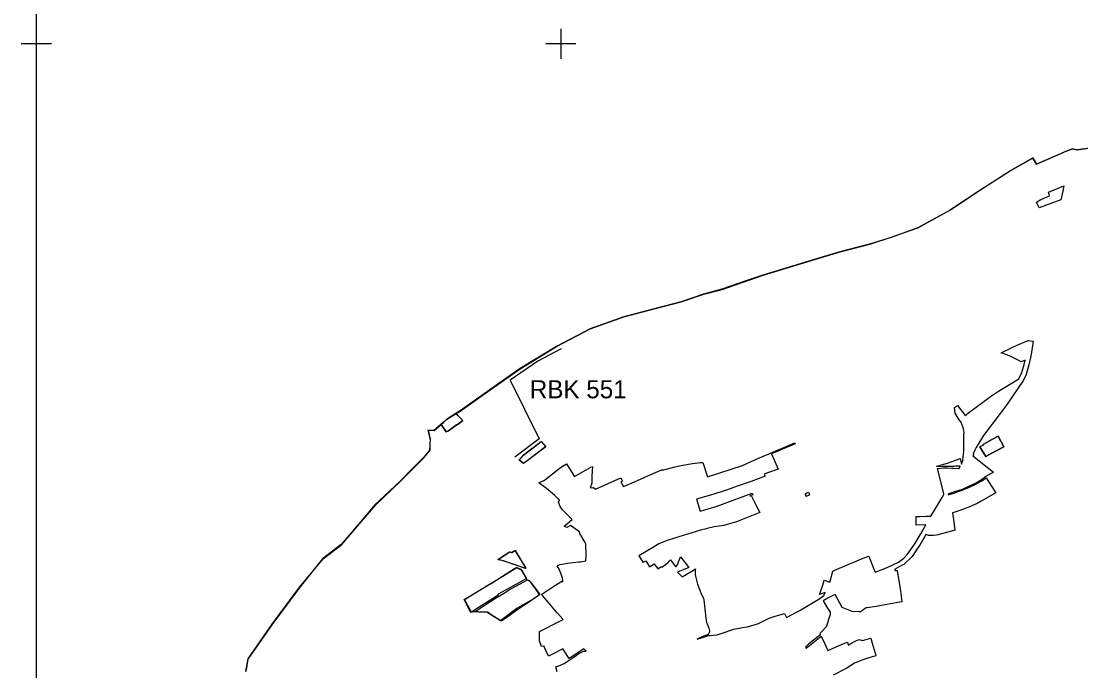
# Model space of a CAD drawing. Extents: x -478490 to -472450, y -1118050 to -1109550.
# Drawn here: x -478490 to -474975, y -1115880 to -1113725 of the extents above; entities that cross this region are included whole.
import ezdxf

# ---------------------------------------------------------------- set-up
doc = ezdxf.new("R2010")
doc.units = 0
for name, color, linetype in [('hranice kú', 7, 'Continuous'), ('Implicitní', 7, 'Continuous'), ('ObPÚ', 7, 'Continuous')]:
    doc.layers.add(name, color=color, linetype=linetype)

msp = doc.modelspace()

# ---------------------------------------------------------------- linework, layer by layer
at = {"layer": 'hranice kú'}
for p, q in [((-475022.9, -1114156.5), (-475122.4, -1114199.6)), ((-475002.4, -1114148.5), (-475022.9, -1114156.5)), ((-474987.2, -1114152.5), (-475002.4, -1114148.5)), ((-474886, -1114137.7), (-474987.2, -1114152.5)), ((-475134, -1114179), (-475207.8, -1114221.5)), ((-475122.4, -1114199.6), (-475134, -1114179)), ((-475207.8, -1114221.5), (-475309.6, -1114286.2)), ((-475309.6, -1114286.2), (-475401.1, -1114346.7)), ((-475401.1, -1114346.7), (-475408.2, -1114351.3)), ((-475408.2, -1114351.3), (-475516.2, -1114410.6)), ((-475516.2, -1114410.6), (-475603.8, -1114442.4)), ((-475603.8, -1114442.4), (-475675.9, -1114464.8)), ((-475748.8, -1114483.6), (-475774.2, -1114490.1)), ((-475675.9, -1114464.8), (-475748.8, -1114483.6)), ((-475851.9, -1114513.6), (-476030.1, -1114567.2)), ((-475774.2, -1114490.1), (-475851.9, -1114513.6)), ((-476089.1, -1114587.7), (-476165.8, -1114614.4)), ((-476030.1, -1114567.2), (-476089.1, -1114587.7)), ((-476165.8, -1114614.4), (-476226.9, -1114630.6)), ((-476300.5, -1114656.1), (-476390.6, -1114678.9)), ((-476226.9, -1114630.6), (-476300.5, -1114656.1)), ((-476390.6, -1114678.9), (-476491.3, -1114705.4)), ((-476491.3, -1114705.4), (-476602.9, -1114745.8)), ((-476602.9, -1114745.8), (-476714.7, -1114803.6)), ((-476714.7, -1114803.6), (-476835.3, -1114877.2)), ((-476835.3, -1114877.2), (-476889.8, -1114915.9)), ((-476889.8, -1114915.9), (-477034.1, -1115017.7)), ((-477079.5, -1115046.1), (-477089.2, -1115054.5)), ((-477047.8, -1115026.2), (-477079.5, -1115046.1)), ((-477034.1, -1115017.7), (-477047.8, -1115026.2)), ((-477121, -1115082.3), (-477141, -1115082)), ((-477141, -1115082), (-477133.6, -1115111.5)), ((-477098.4, -1115062.6), (-477121, -1115082.3)), ((-477089.2, -1115054.5), (-477098.4, -1115062.6)), ((-477133.6, -1115111.5), (-477134.2, -1115129.3)), ((-477134.7, -1115147.1), (-477142.3, -1115156.6)), ((-477134.2, -1115129.3), (-477134.7, -1115147.1)), ((-477155, -1115172.4), (-477210.7, -1115227.9)), ((-477142.3, -1115156.6), (-477155, -1115172.4)), ((-477233.1, -1115250.4), (-477267, -1115282.3)), ((-477229.4, -1115246.9), (-477233.1, -1115250.4)), ((-477216.6, -1115233.9), (-477229.4, -1115246.9)), ((-477214.6, -1115231.9), (-477216.6, -1115233.9)), ((-477210.7, -1115227.9), (-477214.6, -1115231.9)), ((-477267, -1115282.3), (-477317.9, -1115330.4)), ((-477317.9, -1115330.4), (-477350, -1115369.3)), ((-477350, -1115369.3), (-477428.5, -1115460.9)), ((-477428.5, -1115460.9), (-477490.1, -1115508.2)), ((-477490.1, -1115508.2), (-477566.2, -1115601.8)), ((-477566.2, -1115601.8), (-477658.2, -1115726.7)), ((-477658.2, -1115726.7), (-477738.5, -1115840.6)), ((-477738.5, -1115840.6), (-477743.9, -1115876.8)), ((-477743.9, -1115876.8), (-477745.7, -1115882.6))]:
    msp.add_line(p, q, dxfattribs=at)
at = {"layer": 'Implicitní'}
for p, q in [((-478440.1, -1113750.1), (-478440.1, -1113850.1)), ((-478440.1, -1113750.1), (-478440.1, -1113850.1)), ((-478440.1, -1113750.1), (-478440.1, -1113850.1)), ((-478440.1, -1113750.1), (-478440.1, -1113850.1)), ((-478440.1, -1113750.1), (-478440.1, -1113850.1)), ((-478440.1, -1113750.1), (-478440.1, -1113850.1)), ((-478440.1, -1113750.1), (-478440.1, -1113850.1)), ((-476700.1, -1113750.1), (-476700.1, -1113850.1)), ((-476700.1, -1113750.1), (-476700.1, -1113850.1)), ((-476700.1, -1113750.1), (-476700.1, -1113850.1)), ((-476700.1, -1113750.1), (-476700.1, -1113850.1)), ((-476700.1, -1113750.1), (-476700.1, -1113850.1)), ((-476700.1, -1113750.1), (-476700.1, -1113850.1)), ((-476700.1, -1113750.1), (-476700.1, -1113850.1)), ((-478390.1, -1113800.1), (-478490.1, -1113800.1)), ((-478390.1, -1113800.1), (-478490.1, -1113800.1)), ((-478390.1, -1113800.1), (-478490.1, -1113800.1)), ((-478390.1, -1113800.1), (-478490.1, -1113800.1)), ((-478390.1, -1113800.1), (-478490.1, -1113800.1)), ((-478390.1, -1113800.1), (-478490.1, -1113800.1)), ((-476650.1, -1113800.1), (-476750.1, -1113800.1)), ((-476650.1, -1113800.1), (-476750.1, -1113800.1)), ((-476650.1, -1113800.1), (-476750.1, -1113800.1)), ((-476650.1, -1113800.1), (-476750.1, -1113800.1)), ((-476650.1, -1113800.1), (-476750.1, -1113800.1)), ((-476650.1, -1113800.1), (-476750.1, -1113800.1))]:
    msp.add_line(p, q, dxfattribs=at)
msp.add_lwpolyline([(-478440.1, -1118000.1), (-472500.1, -1118000.1), (-472500.1, -1109600.1), (-478440.1, -1109600.1)], close=True, dxfattribs=at)
msp.add_lwpolyline([(-476699, -1114811.9), (-476776, -1114852.7), (-476868.5, -1114915.7), (-476771.5, -1115110.6), (-476852.1, -1115171.5)], dxfattribs=at)
at = {"layer": 'ObPÚ'}
for p, q in [((-476795.8, -1115142.9), (-476765.1, -1115119.2)), ((-476765.1, -1115119.2), (-476749.5, -1115136)), ((-476823.6, -1115164), (-476813.4, -1115156.5)), ((-476813.4, -1115156.5), (-476795.8, -1115142.9)), ((-476749.5, -1115136), (-476807.4, -1115179.7)), ((-476838.6, -1115180.4), (-476823.6, -1115164)), ((-476823.5, -1115192.3), (-476838.6, -1115180.4)), ((-476807.4, -1115179.7), (-476823.5, -1115192.3)), ((-476909, -1115510.7), (-476870.1, -1115484.8)), ((-476870.1, -1115484.8), (-476863.3, -1115487.6)), ((-476863.3, -1115487.6), (-476852.1, -1115480.5)), ((-476852.1, -1115480.5), (-476817.4, -1115537.3)), ((-476900.7, -1115512.2), (-476909, -1115510.7)), ((-476891.2, -1115515.2), (-476900.7, -1115512.2)), ((-476878.5, -1115519.2), (-476891.2, -1115515.2)), ((-476816.7, -1115540.2), (-476878.5, -1115519.2)), ((-476817.4, -1115537.3), (-476816.7, -1115540.2))]:
    msp.add_line(p, q, dxfattribs=at)
for points in [[(-477744.4, -1115881.6), (-477737.4, -1115839.5), (-477657.3, -1115725.4), (-477565.5, -1115600.8), (-477486.9, -1115507), (-477426, -1115461.1), (-477348, -1115368.5), (-477315.2, -1115330.2), (-477231.4, -1115250.6), (-477154.2, -1115173.6), (-477134.2, -1115148.8), (-477133.2, -1115130.3), (-477132.1, -1115111.9), (-477138.9, -1115081.3), (-477119.7, -1115082.7), (-477097.2, -1115062.7), (-477080.6, -1115086.8), (-477072.5, -1115083.8), (-477045.9, -1115063.6), (-477043.9, -1115064.1), (-477025.3, -1115049.6), (-477043.5, -1115030.7), (-477047.5, -1115026.1), (-477033.7, -1115018.2), (-476934, -1114947.9), (-476834.4, -1114877.8), (-476714.6, -1114803.8), (-476602.9, -1114745.9), (-476491.3, -1114705.5), (-476390.2, -1114678.8), (-476300.7, -1114655.7), (-476225.2, -1114630.7), (-476164.4, -1114614.7), (-476028.4, -1114567.7), (-475850.6, -1114513.7), (-475773.2, -1114490.1), (-475675.4, -1114464.4), (-475603.9, -1114441.6), (-475515.6, -1114410.1), (-475407.7, -1114350.6), (-475310.4, -1114285.4), (-475208.2, -1114220.8), (-475134, -1114178.4), (-475121.9, -1114199.1), (-475023.6, -1114156.4), (-475002.8, -1114148.9), (-474998, -1114149.5), (-474990.2, -1114150.6), (-474989.1, -1114150.8), (-474987.5, -1114151), (-474886.4, -1114137.2)], [(-475031.6, -1114270.7), (-475035.2, -1114288.3), (-475041.6, -1114317.3), (-475071, -1114328.2), (-475113.6, -1114343.8), (-475122.4, -1114325.3), (-475107.2, -1114316.9), (-475078.7, -1114304.2), (-475082.7, -1114291.8), (-475031.6, -1114270.7)], [(-475148.1, -1114784.1), (-475132.8, -1114786.1), (-475134.1, -1114794.3), (-475139.6, -1114829.2), (-475141.4, -1114840.6), (-475147, -1114864.5), (-475156.6, -1114896.8), (-475164.7, -1114915.7), (-475219.8, -1114995.7), (-475246.4, -1115030.8), (-475297.9, -1115099.1), (-475322.5, -1115139.2), (-475323.4, -1115141.1), (-475326.2, -1115147.8), (-475332.4, -1115160.1), (-475329.7, -1115162.2), (-475332.8, -1115166.5), (-475264.7, -1115220.3), (-475289.6, -1115235.6), (-475304.6, -1115246.6), (-475313.5, -1115251.8), (-475327.3, -1115259.4), (-475332.9, -1115262), (-475368.8, -1115277.8), (-475390.2, -1115285.2), (-475413.5, -1115293), (-475413.9, -1115295.5), (-475414.6, -1115296.5), (-475396.8, -1115290.7), (-475381.9, -1115285.4), (-475368.1, -1115280.4), (-475352.2, -1115273.9), (-475342, -1115269.3), (-475326, -1115262.1), (-475313, -1115254.8), (-475303.1, -1115249.2), (-475289.4, -1115239.2), (-475271.1, -1115267.1), (-475256.4, -1115289.3), (-475305.6, -1115316.7), (-475319, -1115324.5), (-475352.1, -1115339), (-475379.3, -1115349.1), (-475393.3, -1115353.4), (-475400.3, -1115356), (-475396.5, -1115385.4), (-475392.7, -1115413), (-475404.3, -1115416.8), (-475436.9, -1115425.3), (-475448.5, -1115428.4), (-475454.5, -1115429.6), (-475463.7, -1115430.8), (-475472.8, -1115431.1), (-475479.9, -1115430.5), (-475488.1, -1115428), (-475488.8, -1115427.8), (-475491.2, -1115432.3), (-475508.3, -1115461.2), (-475522.4, -1115482.1), (-475534.8, -1115500.6), (-475562.6, -1115526.6), (-475569.6, -1115530.7), (-475585.2, -1115539.6), (-475592.6, -1115543.6), (-475588.6, -1115546.6), (-475584.2, -1115546.5), (-475575.5, -1115600.7), (-475574.6, -1115607), (-475568.6, -1115650.4), (-475601.1, -1115656.6), (-475624.5, -1115661.2), (-475654.2, -1115666.4), (-475684.3, -1115671.3), (-475687.2, -1115670.6), (-475693.7, -1115674.8), (-475699, -1115680.1), (-475705.7, -1115683.9), (-475709.8, -1115683.9), (-475733.4, -1115683.1), (-475767, -1115669.8), (-475790, -1115626.6), (-475799.8, -1115631.5), (-475804, -1115633.4), (-475810.7, -1115636.7), (-475829.7, -1115648), (-475814.9, -1115672), (-475806.3, -1115684.8), (-475806.3, -1115693.2), (-475811.6, -1115709.7), (-475812.7, -1115712.9), (-475812.9, -1115713.5), (-475819.1, -1115732.4), (-475841.2, -1115755.7), (-475838.5, -1115760.3), (-475845.9, -1115766.1), (-475877.4, -1115790.5)], [(-475218.2, -1114832.5), (-475219.5, -1114831.9), (-475238.7, -1114824.8), (-475202.4, -1114807.1), (-475184, -1114798.8), (-475149.9, -1114784.6), (-475148.1, -1114784.1)], [(-476080.7, -1115733.9), (-476044.6, -1115722.8), (-476009.2, -1115705.3), (-476006, -1115704.3), (-476001.7, -1115702.9), (-475992.1, -1115700.1), (-475958.5, -1115689.8), (-475951, -1115702.6), (-475913.8, -1115682.5), (-475907.2, -1115679.6), (-475903.4, -1115677.7), (-475840.3, -1115639.7), (-475827.1, -1115629.9), (-475826.5, -1115627.2), (-475822.6, -1115620.1), (-475841.5, -1115626.4), (-475831.2, -1115595.6), (-475825.9, -1115579.1), (-475807.2, -1115585.2), (-475804.9, -1115577.5), (-475797.7, -1115549), (-475791.1, -1115546.2), (-475768.3, -1115535.9), (-475744.5, -1115525.5), (-475728.4, -1115519.2), (-475712.4, -1115512.7), (-475696.6, -1115506.6), (-475678, -1115499.1), (-475661.4, -1115542.5), (-475657.5, -1115552.7), (-475617.2, -1115536.5), (-475580, -1115519.1), (-475562.6, -1115505.8), (-475549.8, -1115492.6), (-475525.8, -1115458.2), (-475508.2, -1115428.6), (-475505.8, -1115425), (-475499.2, -1115413), (-475489.2, -1115395.3), (-475521.1, -1115396.7), (-475521.1, -1115367.4), (-475509.5, -1115367.4), (-475488.5, -1115367.2), (-475472.4, -1115366.6), (-475447.9, -1115326.5), (-475434.6, -1115304.4), (-475428.9, -1115294.7), (-475429.3, -1115291.8), (-475450.3, -1115208.5), (-475431.9, -1115206.9), (-475417.8, -1115206.3), (-475403.1, -1115207.2), (-475398.3, -1115207.7), (-475379.8, -1115208.2), (-475378.3, -1115208.3), (-475374.8, -1115201.4), (-475389.4, -1115201.4), (-475396.2, -1115201.5), (-475432.4, -1115201.7), (-475451.6, -1115203.6), (-475452.3, -1115200.8), (-475417.3, -1115191.5), (-475392.6, -1115182.3), (-475375.7, -1115175.9), (-475373.5, -1115183.9), (-475371.1, -1115193.9), (-475364.9, -1115179.2), (-475366.7, -1115178.5), (-475362.9, -1115152.1), (-475362.8, -1115131.7), (-475362.6, -1115116.2), (-475362.9, -1115105.9), (-475363, -1115101.2), (-475363, -1115098.2), (-475361.8, -1115090.2), (-475364.3, -1115077.5), (-475372.3, -1115055.4), (-475379.1, -1115047.3), (-475391.9, -1115024.9), (-475393.8, -1115006.5), (-475383.9, -1114999.9), (-475359.1, -1115032.8), (-475343.3, -1115021.2), (-475301.6, -1114990.1), (-475295.5, -1114985.5), (-475271.4, -1114967.5), (-475248.6, -1114952.7), (-475181.1, -1114910.8), (-475171.1, -1114890.7), (-475163.2, -1114863.4), (-475159.1, -1114849.7), (-475173.1, -1114854.9), (-475181, -1114850.7), (-475198.3, -1114841.7), (-475207.7, -1114837.2), (-475218.2, -1114832.5)], [(-477047.5, -1115026.1), (-477043.5, -1115030.7), (-477025.3, -1115049.6), (-477043.9, -1115064.1), (-477045.9, -1115063.6), (-477072.5, -1115083.8), (-477080.6, -1115086.8), (-477097.2, -1115062.7), (-477088.2, -1115054.8), (-477078.9, -1115046), (-477062.1, -1115035), (-477047.5, -1115026.1)], [(-476765.5, -1115119.5), (-476749.7, -1115136.3), (-476807.4, -1115180.3), (-476823.5, -1115192.5), (-476838.5, -1115180.6), (-476823.2, -1115163.8), (-476813.4, -1115156.1), (-476796, -1115142.8), (-476765.5, -1115119.5)], [(-476755.5, -1115799), (-476755.8, -1115798), (-476764.4, -1115799.6), (-476770.5, -1115780.2), (-476771, -1115765.2), (-476770.2, -1115749.7), (-476741.8, -1115734.8), (-476732, -1115729.7), (-476696.8, -1115711.7), (-476692.5, -1115709.2), (-476710.4, -1115689.4), (-476712.4, -1115687.1), (-476720, -1115678.1), (-476742.3, -1115651.6), (-476761.2, -1115630.1), (-476764.4, -1115626.4), (-476763, -1115625.6), (-476729.7, -1115602.9), (-476697.2, -1115582.4), (-476694.7, -1115586.2), (-476693.6, -1115580.2), (-476694.2, -1115572.8), (-476699.2, -1115558.8), (-476706, -1115542.3), (-476712.2, -1115531.2), (-476708.5, -1115529.6), (-476702.9, -1115527.4), (-476678.2, -1115523.1), (-476641.2, -1115518.6), (-476634.7, -1115517.8), (-476617.1, -1115514.8), (-476616.1, -1115497.4), (-476616.8, -1115459.6), (-476619.4, -1115454.6), (-476636.7, -1115424.2), (-476638.2, -1115419.2), (-476639.6, -1115417.9), (-476648.1, -1115411.8), (-476657.2, -1115405.2), (-476667.7, -1115397.8), (-476668.1, -1115397.6), (-476680.6, -1115404.3), (-476688.9, -1115400.3), (-476683.5, -1115395.6), (-476662.2, -1115377.8), (-476669.9, -1115369.8), (-476680.8, -1115358.9), (-476694.9, -1115346.1), (-476702.3, -1115334.6), (-476708.2, -1115320.9), (-476704.6, -1115313.1), (-476707.2, -1115310.4), (-476710.6, -1115306.8), (-476721, -1115296.9), (-476747.1, -1115275.5), (-476773.1, -1115256.3), (-476753.8, -1115247.8), (-476712.6, -1115214.6), (-476702.4, -1115206.3), (-476694.3, -1115201.1), (-476681.6, -1115192.9), (-476666.8, -1115216), (-476654.4, -1115235.6), (-476600.8, -1115204.3), (-476595.3, -1115201.9), (-476597.5, -1115234), (-476597.6, -1115249.7), (-476597.4, -1115257.5), (-476602.2, -1115273.2), (-476591.8, -1115271.3), (-476584.8, -1115277.5), (-476501, -1115239.4), (-476495.6, -1115250.2), (-476500.4, -1115252.6), (-476492.4, -1115268.6), (-476455.9, -1115252.7), (-476446, -1115248.3), (-476423.8, -1115238.9), (-476408.7, -1115232.4), (-476362.8, -1115211.5), (-476363.1, -1115214.2), (-476329.8, -1115204.9), (-476321.4, -1115203.2), (-476295.6, -1115198.1), (-476262.7, -1115192.2), (-476245.3, -1115189.6), (-476239, -1115188.4), (-476229.4, -1115189.3), (-476228.4, -1115189.3), (-476213.9, -1115236.2), (-476097.8, -1115198.2), (-476044, -1115174.6), (-476040.4, -1115173.1), (-475923.9, -1115123.8), (-475922.9, -1115126.6), (-476001.2, -1115160.1)], [(-476001.2, -1115160.1), (-475978.5, -1115210.4), (-476010.9, -1115222.5), (-476024.9, -1115227.8), (-476022.1, -1115234.1), (-476068.7, -1115252.3), (-476114.9, -1115267.7), (-476138.6, -1115276), (-476141.9, -1115277.2), (-476168.5, -1115286.4), (-476178.6, -1115289.9), (-476195.4, -1115294.7), (-476223, -1115302.6), (-476238.7, -1115307), (-476249.6, -1115310.1), (-476237.8, -1115350.3), (-476184.5, -1115334.3), (-476103.8, -1115304.7), (-476065.3, -1115290.1), (-476062.5, -1115296.4), (-476072.5, -1115299), (-476067.4, -1115300.8), (-476057.5, -1115319.9), (-476052.6, -1115329.4), (-476039.5, -1115354.8), (-476078.4, -1115369.8), (-476117, -1115385.5), (-476155.8, -1115397), (-476158.1, -1115397.3), (-476191.7, -1115401.9), (-476214.9, -1115407.7), (-476217.9, -1115408.5), (-476236.6, -1115413.2), (-476323, -1115439.7), (-476350.1, -1115449), (-476375, -1115459), (-476385.9, -1115464.8), (-476392.2, -1115469.7), (-476411, -1115480.8), (-476441.4, -1115498.3), (-476428.9, -1115516.6), (-476426.7, -1115520.2), (-476425.5, -1115519.4), (-476418.1, -1115514.4), (-476406.1, -1115534.8), (-476390, -1115524.6), (-476377.8, -1115542), (-476366.1, -1115533.4), (-476364.4, -1115535.6), (-476361.5, -1115533.8), (-476342.9, -1115519.2), (-476343.8, -1115517.9), (-476335.7, -1115511.8), (-476321.2, -1115532.1), (-476318.9, -1115534.9), (-476313, -1115528.6), (-476309.8, -1115518.6), (-476305.3, -1115506.9), (-476302.5, -1115502), (-476275.6, -1115537.5), (-476313.2, -1115552.2), (-476300.2, -1115565.6), (-476297.2, -1115568.2), (-476265.8, -1115548.7), (-476253.2, -1115541.5), (-476254.2, -1115545.1), (-476254.1, -1115560.3), (-476252.9, -1115565.5), (-476247.1, -1115591.9), (-476235, -1115620.9), (-476233.9, -1115623.6), (-476227.1, -1115639.9), (-476225.4, -1115644.4), (-476220, -1115694.3), (-476219.8, -1115696.3), (-476219.6, -1115698.6), (-476218.9, -1115704.2), (-476216.5, -1115719.8), (-476214.9, -1115724.1), (-476208.9, -1115738.8), (-476206.5, -1115747), (-476206.4, -1115750.3), (-476211.4, -1115759.3), (-476232.4, -1115767.1), (-476247.2, -1115775.1), (-476229.9, -1115769.6), (-476218.5, -1115766.3), (-476210.1, -1115762.7), (-476205.2, -1115762.3), (-476193.3, -1115761.9), (-476181.7, -1115759.9), (-476167.6, -1115755.9), (-476126.1, -1115741.6), (-476097.4, -1115735.9), (-476082.4, -1115734.1), (-476080.7, -1115733.9)], [(-475878.6, -1115287.3), (-475875.6, -1115294.7), (-475876.6, -1115295.2), (-475876.2, -1115296.1), (-475875.8, -1115297), (-475885.9, -1115301.2), (-475886.3, -1115300.2), (-475888.6, -1115293.7), (-475887, -1115293.1), (-475887.8, -1115291.1), (-475878.6, -1115287.3)], [(-476851.2, -1115480.9), (-476816.7, -1115537.6), (-476815.9, -1115540.5), (-476877.8, -1115519.3), (-476890.3, -1115515.3), (-476899.7, -1115512.3), (-476908, -1115510.6), (-476869, -1115484.9), (-476862.3, -1115487.4), (-476851.2, -1115480.9)], [(-476845.8, -1115536.8), (-476833.2, -1115543.1), (-476830.3, -1115545.2), (-476814.1, -1115573.4), (-476829.7, -1115582.6), (-476871.8, -1115606), (-476907.9, -1115625.4), (-476911.4, -1115631), (-476914.7, -1115633.2), (-476935, -1115646.2), (-476979.5, -1115674.5), (-476996.8, -1115685.2), (-477019.2, -1115643.1), (-476956.1, -1115604.4), (-476941.7, -1115595.5), (-476928.8, -1115587.7), (-476892.8, -1115565.7), (-476851.6, -1115540.4), (-476845.8, -1115536.8)], [(-476810.1, -1115578.3), (-476805.9, -1115579.4), (-476804.7, -1115580.3), (-476803.4, -1115582.1), (-476792.3, -1115597.6), (-476773.7, -1115623.2), (-476770.2, -1115628.1), (-476787.4, -1115639.3), (-476804.2, -1115650.6), (-476823.1, -1115663.3), (-476837.9, -1115672.8), (-476847.1, -1115679.5), (-476850.6, -1115681.9), (-476879.3, -1115702.4), (-476896.2, -1115714.4), (-476899, -1115714.2), (-476930.7, -1115694), (-476942.5, -1115685.1), (-476965.9, -1115685.2), (-476984.4, -1115683.5), (-476947.9, -1115658.3), (-476916.7, -1115638.9), (-476890.7, -1115623.1), (-476880.5, -1115616.9), (-476873.4, -1115612.5), (-476851.1, -1115600.2), (-476833, -1115590.3), (-476824.8, -1115585.7), (-476813, -1115578.7), (-476810.1, -1115578.3)], [(-475877.4, -1115790.5), (-475888.6, -1115801.4), (-475886, -1115804.2), (-475836, -1115764.4), (-475833.6, -1115770.2), (-475830.2, -1115777.9), (-475814.8, -1115812), (-475761.7, -1115789.4), (-475749.3, -1115784.9), (-475746.8, -1115794.7), (-475738, -1115789.5), (-475721.7, -1115779.9), (-475710.7, -1115775.7), (-475699.7, -1115779.1), (-475672.1, -1115771.2), (-475667.3, -1115787.5), (-475657.2, -1115821.4), (-475656.6, -1115823.4), (-475654.6, -1115830.4), (-475677.9, -1115836.7), (-475698.4, -1115843.4), (-475726.3, -1115854.9), (-475753.2, -1115871.8), (-475796.4, -1115894.5)], [(-476712.4, -1115883.4), (-476716.3, -1115867), (-476706.5, -1115862.8), (-476689.2, -1115855), (-476672.4, -1115844.1), (-476656.2, -1115833.3), (-476639.8, -1115822.5), (-476624.6, -1115814.3), (-476615.7, -1115814.8), (-476624, -1115806.8), (-476672.6, -1115838.9), (-476693.6, -1115807.2), (-476722.7, -1115821.8), (-476740.9, -1115830.8), (-476754.6, -1115802.9), (-476755.5, -1115799)]]:
    msp.add_lwpolyline(points, dxfattribs=at)
for points in [[(-475309.6, -1115137.3), (-475298.3, -1115130.6), (-475298.9, -1115129.2), (-475268.3, -1115111.9), (-475249.1, -1115101.1), (-475230.6, -1115137.3), (-475253.9, -1115149.2), (-475272, -1115158.9), (-475280.6, -1115163.6), (-475290, -1115168.6)], [(-475309.6, -1115137.3), (-475290, -1115168.6), (-475280.6, -1115163.6), (-475272, -1115158.9), (-475253.9, -1115149.2), (-475230.6, -1115137.3), (-475249.1, -1115101.1), (-475268.3, -1115111.9), (-475298.9, -1115129.2), (-475298.3, -1115130.6)], [(-476847.1, -1115536.5), (-476831.3, -1115545), (-476814.5, -1115573.1), (-476813.5, -1115578.5), (-476810.5, -1115578.2), (-476806.2, -1115579.8), (-476803.9, -1115582.7), (-476792.3, -1115597.2), (-476773, -1115622.4), (-476769.2, -1115626.6), (-476786.4, -1115638.9), (-476824.6, -1115661), (-476839.5, -1115669.7), (-476846, -1115673.3), (-476899.9, -1115714.2), (-476935.6, -1115692.1), (-476945.3, -1115684.7), (-476973.5, -1115685.2), (-476986, -1115684.2), (-476998.5, -1115686), (-477020.9, -1115643.5), (-476943, -1115597.1), (-476931.4, -1115590.2), (-476893.5, -1115566.1), (-476853.3, -1115540.3)]]:
    msp.add_lwpolyline(points, close=True, dxfattribs=at)

# ---------------------------------------------------------------- texts
at = {"layer": 'Implicitní'}
msp.add_text('RBK 551', height=60, dxfattribs=at).set_placement((-476802.8, -1114975.8))

doc.saveas('drawing.dxf')
